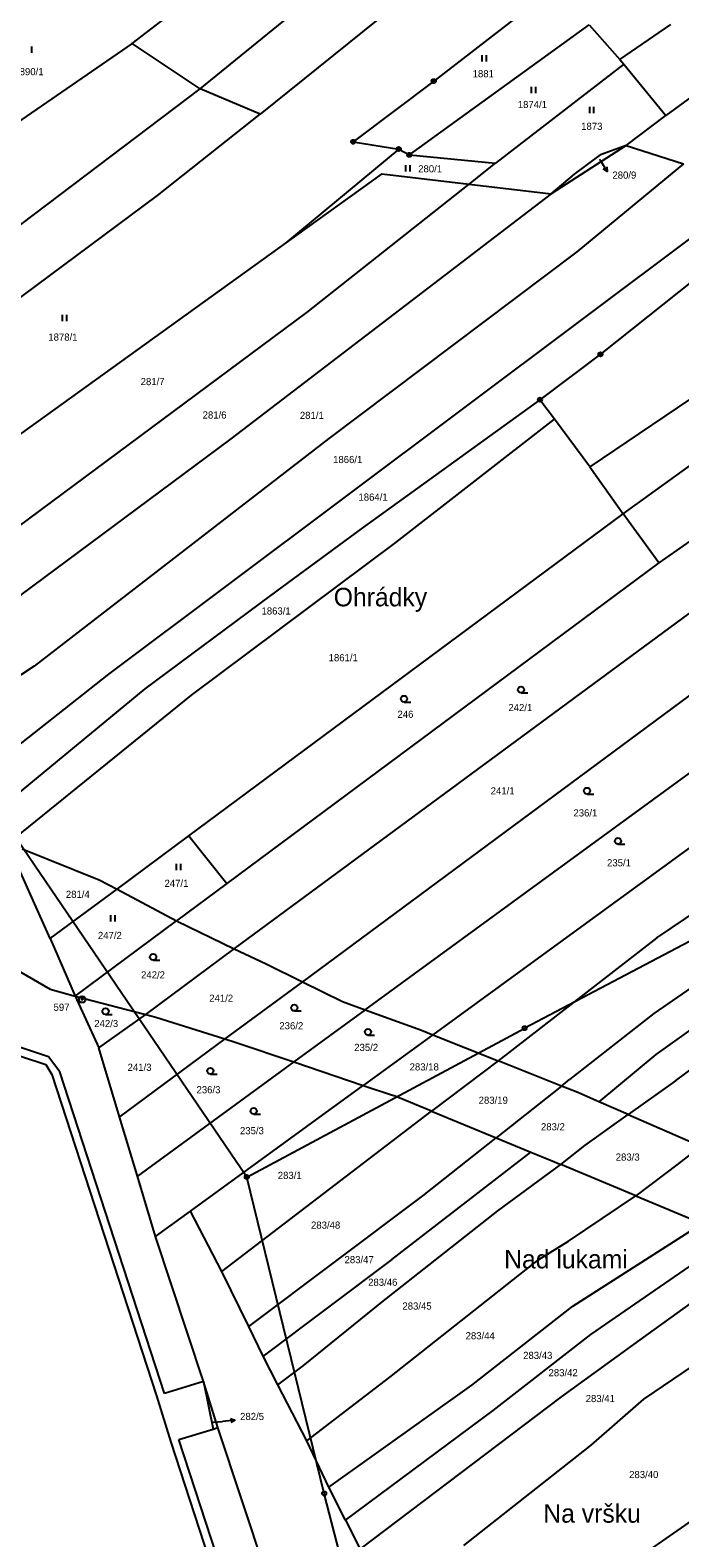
# Model space of a CAD drawing. Extents: x -762263 to -760336, y -1154405 to -1152076.
# Drawn here: x -761696.3 to -761541.7, y -1152988.8 to -1152630.1 of the extents above; entities that cross this region are included whole.
import ezdxf

# ---------------------------------------------------------------- set-up
doc = ezdxf.new("R2010")
doc.units = 0
for name, color, linetype in [('Vrstva 1', 7, 'Continuous'), ('Vrstva 12', 7, 'Continuous'), ('Vrstva 15', 7, 'Continuous'), ('Vrstva 16', 7, 'Continuous'), ('Vrstva 17', 7, 'Continuous'), ('Vrstva 18', 7, 'Continuous'), ('Vrstva 24', 7, 'Continuous'), ('Vrstva 25', 7, 'Continuous'), ('Vrstva 26', 7, 'Continuous'), ('Vrstva 6', 7, 'Continuous')]:
    doc.layers.add(name, color=color, linetype=linetype)

msp = doc.modelspace()

# ---------------------------------------------------------------- linework, layer by layer
at = {"layer": 'Vrstva 1'}
for p, q in [((-761506.46, -1152622.12), (-761545.06, -1152650.41)), ((-761563.31, -1152628.83), (-761555.97, -1152637.06)), ((-761555.97, -1152637.06), (-761543.8, -1152628.75)), ((-761555.97, -1152637.06), (-761555.04, -1152638.2)), ((-761555.04, -1152638.2), (-761545.06, -1152650.41)), ((-761554.48, -1152657.55), (-761545.06, -1152650.41)), ((-761554.48, -1152657.55), (-761572.29, -1152669.04)), ((-761554.48, -1152657.55), (-761540.81, -1152661.88)), ((-761612.65, -1152664.29), (-761635.48, -1152680.7)), ((-761612.65, -1152664.29), (-761591.8, -1152666.74)), ((-761591.8, -1152666.74), (-761572.29, -1152669.04)), ((-761635.48, -1152680.7), (-761734.11, -1152751.6)), ((-761534.53, -1152686.45), (-761560.58, -1152707.21)), ((-761513.57, -1152700.44), (-761563.12, -1152733.98)), ((-761560.58, -1152707.21), (-761574.98, -1152718.01)), ((-761571.52, -1152722.67), (-761574.98, -1152718.01)), ((-761555.22, -1152745.2), (-761516.73, -1152717.36)), ((-761563.12, -1152733.98), (-761571.52, -1152722.67)), ((-761509.17, -1152730.62), (-761546.71, -1152756.81)), ((-761563.12, -1152733.98), (-761555.22, -1152745.2)), ((-761658.53, -1152821.77), (-761555.22, -1152745.2)), ((-761546.71, -1152756.81), (-761555.22, -1152745.2)), ((-761546.71, -1152756.81), (-761649.5, -1152833.11)), ((-761647.74, -1152848.64), (-761539.5, -1152768.89)), ((-761530.76, -1152781.96), (-761631.52, -1152856.45)), ((-761616.57, -1152863.14), (-761522.15, -1152794.2)), ((-761513.77, -1152805.94), (-761600.5, -1152869.06)), ((-761675.64, -1152834.45), (-761658.53, -1152821.77)), ((-761658.53, -1152821.77), (-761649.5, -1152833.11)), ((-761691.51, -1152846.21), (-761701.64, -1152823.7)), ((-761698.2, -1152824.84), (-761679.85, -1152832.21)), ((-761679.85, -1152832.21), (-761675.64, -1152834.45)), ((-761691.51, -1152846.21), (-761675.64, -1152834.45)), ((-761675.64, -1152834.45), (-761661.47, -1152842)), ((-761649.5, -1152833.11), (-761661.47, -1152842)), ((-761685.6, -1152859.87), (-761661.47, -1152842)), ((-761661.47, -1152842), (-761647.74, -1152848.64)), ((-761691.51, -1152846.21), (-761685.6, -1152859.87)), ((-761668.81, -1152864.23), (-761647.74, -1152848.64)), ((-761647.74, -1152848.64), (-761640.13, -1152852.19)), ((-761704.08, -1152851.01), (-761691.53, -1152858.2)), ((-761640.13, -1152852.19), (-761631.52, -1152856.45)), ((-761631.52, -1152856.45), (-761649.95, -1152870.07)), ((-761631.52, -1152856.45), (-761621.99, -1152861.17)), ((-761691.53, -1152858.2), (-761685.6, -1152859.87)), ((-761685.6, -1152859.87), (-761668.81, -1152864.23)), ((-761685.6, -1152859.87), (-761679.94, -1152872.17)), ((-761621.99, -1152861.17), (-761616.57, -1152863.14)), ((-761679.94, -1152872.17), (-761668.81, -1152864.23)), ((-761668.81, -1152864.23), (-761666.38, -1152864.87)), ((-761666.38, -1152864.87), (-761649.95, -1152870.07)), ((-761616.57, -1152863.14), (-761633.55, -1152875.54)), ((-761616.57, -1152863.14), (-761603.2, -1152867.99)), ((-761603.2, -1152867.99), (-761600.5, -1152869.06)), ((-761704.92, -1152872.08), (-761692.6, -1152876.19)), ((-761691.97, -1152874.29), (-761704.12, -1152870.25)), ((-761675.04, -1152888.62), (-761679.94, -1152872.17)), ((-761649.95, -1152870.07), (-761675.04, -1152888.62)), ((-761649.95, -1152870.07), (-761647.29, -1152870.91)), ((-761647.29, -1152870.91), (-761633.55, -1152875.54)), ((-761600.5, -1152869.06), (-761617.05, -1152881.11)), ((-761600.5, -1152869.06), (-761584.91, -1152875.28)), ((-761689.25, -1152877.89), (-761691.97, -1152874.29)), ((-761633.55, -1152875.54), (-761670.76, -1152902.71)), ((-761633.55, -1152875.54), (-761617.05, -1152881.11)), ((-761584.91, -1152875.28), (-761600.83, -1152887.24)), ((-761569.88, -1152881.28), (-761584.91, -1152875.28)), ((-761692.6, -1152876.19), (-761691.16, -1152878.51)), ((-761691.16, -1152878.51), (-761666.23, -1152954.98)), ((-761664.32, -1152954.39), (-761689.25, -1152877.89)), ((-761658.17, -1152911.03), (-761617.05, -1152881.11)), ((-761617.05, -1152881.11), (-761609.87, -1152883.53)), ((-761569.88, -1152881.28), (-761585.41, -1152893.58)), ((-761566.01, -1152882.82), (-761569.88, -1152881.28)), ((-761561, -1152885), (-761566.01, -1152882.82)), ((-761600.83, -1152887.24), (-761609.87, -1152883.53)), ((-761553.98, -1152888.06), (-761561, -1152885)), ((-761670.76, -1152902.71), (-761675.04, -1152888.62)), ((-761600.83, -1152887.24), (-761585.41, -1152893.58)), ((-761564.3, -1152895.46), (-761553.98, -1152888.06)), ((-761553.98, -1152888.06), (-761536.69, -1152895.6)), ((-761585.41, -1152893.58), (-761577.13, -1152896.98)), ((-761577.13, -1152896.98), (-761572.47, -1152898.89)), ((-761570.01, -1152899.92), (-761564.3, -1152895.46)), ((-761536.69, -1152895.6), (-761542.07, -1152899.78)), ((-761572.47, -1152898.89), (-761570.01, -1152899.92)), ((-761552.17, -1152907.36), (-761570.01, -1152899.92)), ((-761542.07, -1152899.78), (-761552.17, -1152907.36)), ((-761666.48, -1152917.08), (-761670.76, -1152902.71)), ((-761552.17, -1152907.36), (-761536.35, -1152913.95)), ((-761666.48, -1152917.08), (-761658.17, -1152911.03)), ((-761655.05, -1152951.53), (-761666.48, -1152917.08)), ((-761655.05, -1152951.53), (-761664.32, -1152954.39)), ((-761651.66, -1152962.52), (-761655.05, -1152951.53)), ((-761666.23, -1152954.98), (-761662.84, -1152965.97)), ((-761660.93, -1152965.38), (-761652.77, -1152962.86)), ((-761639.47, -1153030.9), (-761660.93, -1152965.38)), ((-761652.77, -1152962.86), (-761651.66, -1152962.52)), ((-761627.98, -1153033.79), (-761651.66, -1152962.52)), ((-761662.84, -1152965.97), (-761641.37, -1153031.52))]:
    msp.add_line(p, q, dxfattribs=at)
at = {"layer": 'Vrstva 12'}
for p, q in [((-761644.75, -1152902.92), (-761709.8, -1152807.49)), ((-761510.52, -1152831.73), (-761578.61, -1152867.5)), ((-761644.75, -1152902.92), (-761578.61, -1152867.5)), ((-761626.33, -1152978.19), (-761644.75, -1152902.92)), ((-761604.96, -1153060.88), (-761626.33, -1152978.19))]:
    msp.add_line(p, q, dxfattribs=at)
at = {"layer": 'Vrstva 16'}
for p, q in [((-761560.7, -1152660.89), (-761560.53, -1152661.16)), ((-761558.976, -1152663.726), (-761560.53, -1152661.16)), ((-761652.72, -1152961.27), (-761650.56, -1152961.04)), ((-761647.577, -1152960.721), (-761650.56, -1152961.04))]:
    msp.add_line(p, q, dxfattribs=at)
for points in [[(-761559.066, -1152662.612), (-761558.976, -1152663.726), (-761559.922, -1152663.13)], [(-761648.625, -1152960.33), (-761647.577, -1152960.721), (-761648.518, -1152961.324)]]:
    msp.add_lwpolyline(points, dxfattribs=at)
at = {"layer": 'Vrstva 24'}
for centre, radius in [((-761600.26, -1152642.23), 0.5), ((-761600.26, -1152642.23), 0.1), ((-761619.44, -1152656.66), 0.5), ((-761619.44, -1152656.66), 0.1), ((-761608.58, -1152658.38), 0.5), ((-761608.58, -1152658.38), 0.1), ((-761606.07, -1152659.78), 0.5), ((-761606.07, -1152659.78), 0.1), ((-761560.58, -1152707.21), 0.5), ((-761560.58, -1152707.21), 0.1), ((-761574.98, -1152718.01), 0.5), ((-761574.98, -1152718.01), 0.1), ((-761683.92, -1152860.68), 0.75), ((-761683.92, -1152860.68), 0.1)]:
    msp.add_circle(centre, radius, dxfattribs=at)
at = {"layer": 'Vrstva 25'}
for p, q in [((-761695.94, -1152635.47), (-761695.94, -1152633.97)), ((-761588.7, -1152637.59), (-761588.7, -1152636.09)), ((-761587.7, -1152637.59), (-761587.7, -1152636.09)), ((-761576.97, -1152645.09), (-761576.97, -1152643.59)), ((-761575.97, -1152645.09), (-761575.97, -1152643.59)), ((-761563.14, -1152649.83), (-761563.14, -1152648.33)), ((-761562.14, -1152649.83), (-761562.14, -1152648.33)), ((-761606.9, -1152663.7), (-761606.9, -1152662.2)), ((-761605.9, -1152663.7), (-761605.9, -1152662.2)), ((-761688.61, -1152699.3), (-761688.61, -1152697.8)), ((-761687.61, -1152699.3), (-761687.61, -1152697.8)), ((-761579.49, -1152787.75), (-761577.89, -1152787.75)), ((-761607.32, -1152789.93), (-761605.72, -1152789.93)), ((-761563.78, -1152811.81), (-761562.18, -1152811.81)), ((-761556.42, -1152823.74), (-761554.82, -1152823.74)), ((-761661.46, -1152829.94), (-761661.46, -1152828.44)), ((-761660.46, -1152829.94), (-761660.46, -1152828.44)), ((-761677.09, -1152842.16), (-761677.09, -1152840.66)), ((-761676.09, -1152842.16), (-761676.09, -1152840.66)), ((-761667.04, -1152851.34), (-761665.44, -1152851.34)), ((-761678.37, -1152864.25), (-761676.77, -1152864.25)), ((-761633.43, -1152863.42), (-761631.83, -1152863.42)), ((-761615.93, -1152869.17), (-761614.33, -1152869.17)), ((-761653.41, -1152878.44), (-761651.81, -1152878.44)), ((-761643.1, -1152887.98), (-761641.5, -1152887.98))]:
    msp.add_line(p, q, dxfattribs=at)
for centre in [(-761607.32, -1152789.18), (-761579.49, -1152787), (-761563.78, -1152811.06), (-761556.42, -1152822.99), (-761667.04, -1152850.59), (-761678.37, -1152863.5), (-761633.43, -1152862.67), (-761615.93, -1152868.42), (-761653.41, -1152877.69), (-761643.1, -1152887.23)]:
    msp.add_circle(centre, 0.75, dxfattribs=at)
at = {"layer": 'Vrstva 26'}
for centre in [(-761578.61, -1152867.5), (-761644.75, -1152902.92), (-761626.33, -1152978.19)]:
    msp.add_circle(centre, 0.5, dxfattribs=at)
at = {"layer": 'Vrstva 6'}
for p, q in [((-761583.91, -1152603.67), (-761641.55, -1152650.06)), ((-761672.04, -1152633.28), (-761639.98, -1152608.57)), ((-761655.88, -1152644.04), (-761616.31, -1152611.88)), ((-761570.74, -1152619.41), (-761600.26, -1152642.23)), ((-761606.07, -1152659.78), (-761563.31, -1152628.83)), ((-761672.04, -1152633.28), (-761749.48, -1152686.56)), ((-761655.88, -1152644.04), (-761672.04, -1152633.28)), ((-761555.04, -1152638.2), (-761585.55, -1152661.77)), ((-761600.26, -1152642.23), (-761619.44, -1152656.66)), ((-761705.17, -1152681.31), (-761655.88, -1152644.04)), ((-761641.55, -1152650.06), (-761655.88, -1152644.04)), ((-761665.99, -1152669.46), (-761641.55, -1152650.06)), ((-761619.44, -1152656.66), (-761608.58, -1152658.38)), ((-761608.58, -1152658.38), (-761635.48, -1152680.7)), ((-761608.58, -1152658.38), (-761606.07, -1152659.78)), ((-761606.07, -1152659.78), (-761585.55, -1152661.77)), ((-761566.78, -1152664.36), (-761560.59, -1152659.79)), ((-761554.48, -1152657.55), (-761560.59, -1152659.79)), ((-761591.8, -1152666.74), (-761585.55, -1152661.77)), ((-761540.81, -1152661.88), (-761566.2, -1152682.83)), ((-761630.46, -1152697.29), (-761591.8, -1152666.74)), ((-761572.29, -1152669.04), (-761566.78, -1152664.36)), ((-761722.61, -1152711.41), (-761665.99, -1152669.46)), ((-761572.29, -1152669.04), (-761648.55, -1152727.31)), ((-761537.16, -1152678.07), (-761677.64, -1152783.3)), ((-761566.2, -1152682.83), (-761625.2, -1152727.27)), ((-761726.5, -1152768.5), (-761630.46, -1152697.29)), ((-761574.98, -1152718.01), (-761617.56, -1152748.7)), ((-761609.28, -1152751.98), (-761571.52, -1152722.67)), ((-761648.55, -1152727.31), (-761720.86, -1152781.03)), ((-761625.2, -1152727.27), (-761695.32, -1152781.37)), ((-761617.56, -1152748.7), (-761639.14, -1152764.61)), ((-761657.88, -1152788.29), (-761609.28, -1152751.98)), ((-761639.14, -1152764.61), (-761669.03, -1152786.8)), ((-761695.32, -1152781.37), (-761714.94, -1152794.16)), ((-761677.64, -1152783.3), (-761708.78, -1152807.84)), ((-761669.03, -1152786.8), (-761704.93, -1152816.38)), ((-761701.64, -1152823.7), (-761657.88, -1152788.29)), ((-761547.2, -1152846.06), (-761486.39, -1152804.93)), ((-761503.4, -1152833.34), (-761547.91, -1152863.99)), ((-761498.02, -1152838.47), (-761547.43, -1152873.8)), ((-761547.2, -1152846.06), (-761584.91, -1152875.28)), ((-761542.75, -1152880.01), (-761501.78, -1152849.8)), ((-761547.91, -1152863.99), (-761567.94, -1152879.74)), ((-761547.43, -1152873.8), (-761561, -1152885)), ((-761569.88, -1152881.28), (-761567.94, -1152879.74)), ((-761542.75, -1152880.01), (-761553.98, -1152888.06)), ((-761650.68, -1152925.36), (-761600.83, -1152887.24)), ((-761602.89, -1152907.42), (-761585.41, -1152893.58)), ((-761610.21, -1152922.57), (-761577.13, -1152896.98)), ((-761585.01, -1152910.98), (-761570.01, -1152899.92)), ((-761644.25, -1152938.48), (-761602.89, -1152907.42)), ((-761568.17, -1152918.14), (-761552.17, -1152907.36)), ((-761650.68, -1152925.36), (-761658.17, -1152911.03)), ((-761612.64, -1152932.69), (-761585.01, -1152910.98)), ((-761567.14, -1152933.62), (-761536.35, -1152913.95)), ((-761575.24, -1152922.53), (-761568.17, -1152918.14)), ((-761562.87, -1152940.38), (-761529.44, -1152917.29)), ((-761551.11, -1152941.64), (-761522.42, -1152920.93)), ((-761644.25, -1152938.48), (-761650.68, -1152925.36)), ((-761610.21, -1152922.57), (-761640.82, -1152945.52)), ((-761610.75, -1152950.49), (-761575.24, -1152922.53)), ((-761550.29, -1152955.78), (-761509.05, -1152927.85)), ((-761631.36, -1152947.83), (-761612.64, -1152932.69)), ((-761591.17, -1152952.45), (-761567.14, -1152933.62)), ((-761640.82, -1152945.52), (-761644.25, -1152938.48)), ((-761586.13, -1152958.48), (-761562.87, -1152940.38)), ((-761569.83, -1152955.23), (-761551.11, -1152941.64)), ((-761637.35, -1152952.37), (-761640.82, -1152945.52)), ((-761637.35, -1152952.37), (-761631.36, -1152947.83)), ((-761630.5, -1152965.67), (-761610.75, -1152950.49)), ((-761655.05, -1152951.53), (-761652.77, -1152962.86)), ((-761630.5, -1152965.67), (-761637.35, -1152952.37)), ((-761625.24, -1152976.66), (-761591.17, -1152952.45)), ((-761617.77, -1152991.45), (-761569.83, -1152955.23)), ((-761562.78, -1152966.67), (-761550.29, -1152955.78)), ((-761621.23, -1152984.57), (-761586.13, -1152958.48)), ((-761625.24, -1152976.66), (-761630.5, -1152965.67)), ((-761593.11, -1152990.58), (-761562.78, -1152966.67)), ((-761621.23, -1152984.57), (-761625.24, -1152976.66)), ((-761530.07, -1152978.48), (-761560.47, -1152999.59)), ((-761621.23, -1152984.57), (-761617.77, -1152991.45))]:
    msp.add_line(p, q, dxfattribs=at)

# ---------------------------------------------------------------- texts
at = {"layer": 'Vrstva 15'}
for s, p in [('Ohrádky', (-761624.065, -1152767.17)), ('Nad lukami', (-761583.514, -1152924.66)), ('Na vršku', (-761574.187, -1152985.14))]:
    msp.add_text(s, height=4.4, dxfattribs=at).set_placement(p)
at = {"layer": 'Vrstva 16'}
for s, p in [('280/9', (-761557.743, -1152665.43)), ('282/5', (-761646.343, -1152960.72))]:
    msp.add_text(s, height=1.7, dxfattribs=at).set_placement(p)
at = {"layer": 'Vrstva 17'}
msp.add_text('597', height=1.7, dxfattribs=at).set_placement((-761690.737, -1152863.38))
at = {"layer": 'Vrstva 18'}
for s, height, p in [('1890/1', 1.7, (-761700.07, -1152640.83)), ('1881', 1.7, (-761591.001, -1152641.32)), ('1874/1', 1.7, (-761580.263, -1152648.64)), ('1873', 1.7, (-761565.179, -1152653.83)), ('280/1', 1.7, (-761603.962, -1152663.94)), ('280/9', 0.1, (-761560.909, -1152660.89)), ('1878/1', 1.7, (-761691.99, -1152703.97)), ('281/7', 1.7, (-761670.005, -1152714.55)), ('281/6', 1.7, (-761655.256, -1152722.5)), ('281/1', 1.7, (-761632.118, -1152722.59)), ('1866/1', 1.7, (-761624.213, -1152733.09)), ('1864/1', 1.7, (-761618.183, -1152742.03)), ('1863/1', 1.7, (-761641.25, -1152769.12)), ('1861/1', 1.7, (-761625.275, -1152780.23)), ('246', 1.7, (-761608.893, -1152793.69)), ('242/1', 1.7, (-761582.503, -1152792.1)), ('241/1', 1.7, (-761586.713, -1152811.91)), ('236/1', 1.7, (-761567.013, -1152817.15)), ('235/1', 1.7, (-761559.023, -1152829.02)), ('247/1', 1.7, (-761664.333, -1152833.9)), ('281/4', 1.7, (-761687.813, -1152836.51)), ('247/2', 1.7, (-761680.183, -1152846.3)), ('242/2', 1.7, (-761669.913, -1152855.68)), ('241/2', 1.7, (-761653.693, -1152861.23)), ('242/3', 1.7, (-761681.053, -1152867.25)), ('236/2', 1.7, (-761637.003, -1152867.78)), ('235/2', 1.7, (-761619.183, -1152872.93)), ('241/3', 1.7, (-761673.113, -1152877.67)), ('283/18', 1.7, (-761606.003, -1152877.57)), ('236/3', 1.7, (-761656.713, -1152883)), ('283/19', 1.7, (-761589.572, -1152885.5)), ('283/2', 1.7, (-761574.744, -1152891.82)), ('235/3', 1.7, (-761646.373, -1152892.74)), ('283/3', 1.7, (-761556.948, -1152899.02)), ('283/1', 1.7, (-761637.383, -1152903.38)), ('283/48', 1.7, (-761629.47, -1152915.21)), ('283/47', 1.7, (-761621.49, -1152923.42)), ('283/46', 1.7, (-761615.87, -1152928.8)), ('283/45', 1.7, (-761607.717, -1152934.46)), ('283/44', 1.7, (-761592.68, -1152941.53)), ('283/43', 1.7, (-761578.987, -1152946.2)), ('283/42', 1.7, (-761572.944, -1152950.31)), ('283/41', 1.7, (-761564.102, -1152956.46)), ('282/5', 0.1, (-761652.935, -1152961.27)), ('283/40', 1.7, (-761553.757, -1152974.54))]:
    msp.add_text(s, height=height, dxfattribs=at).set_placement(p)

doc.saveas('drawing.dxf')
